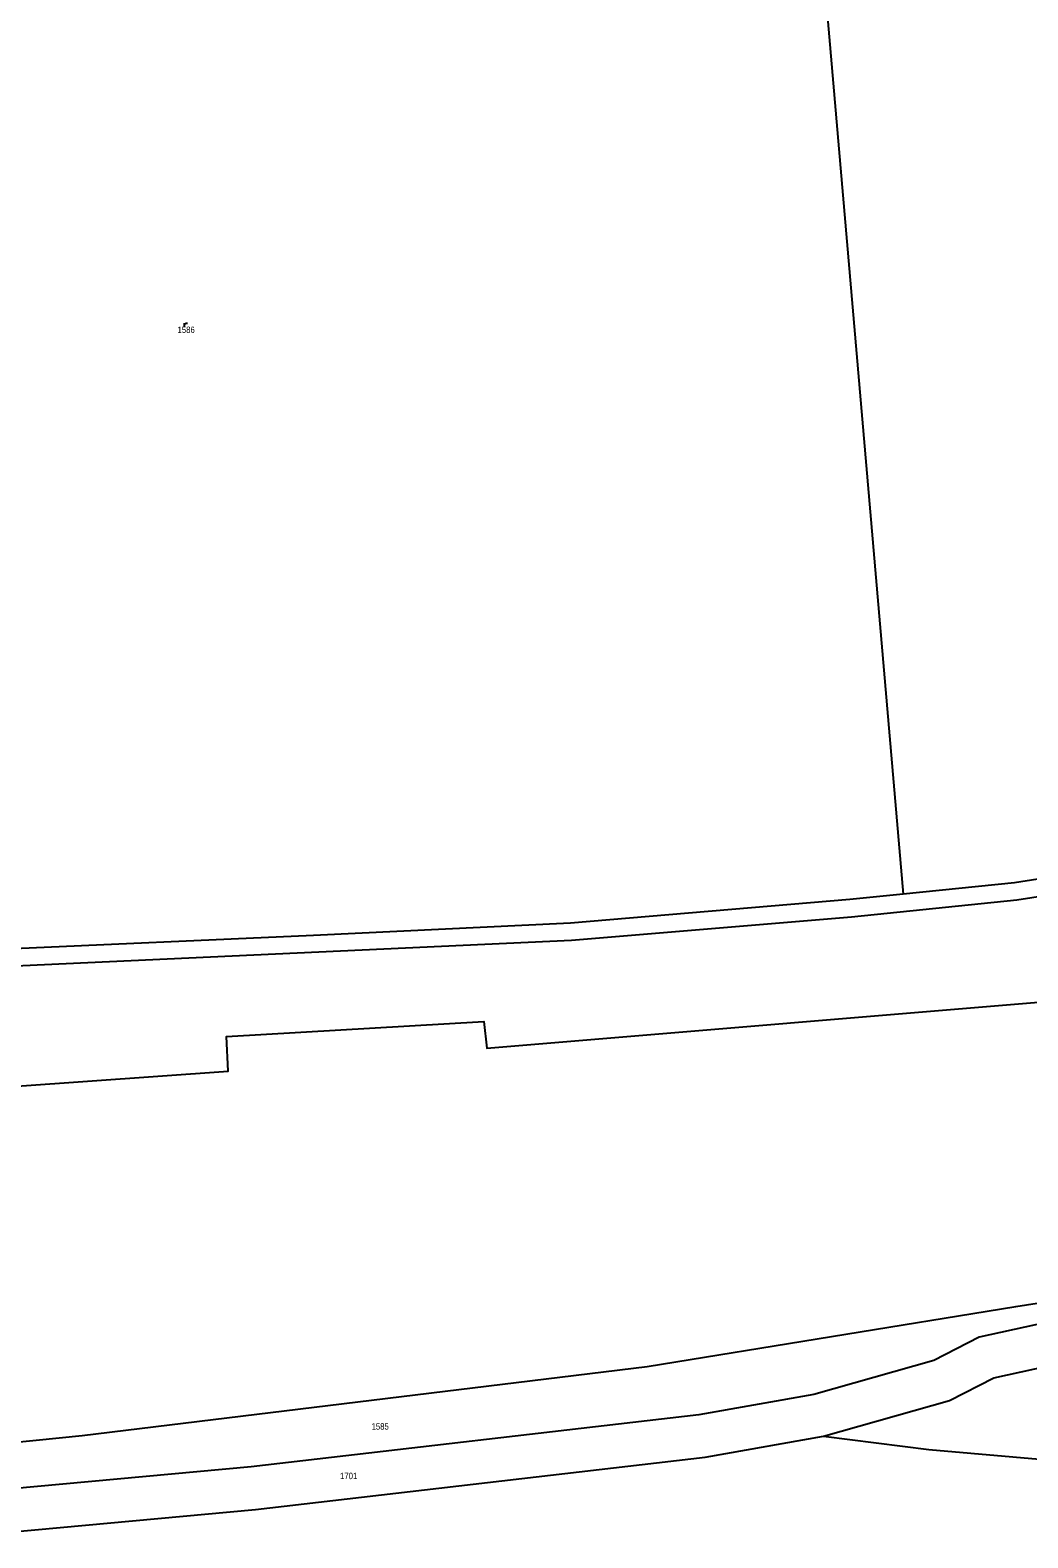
# Model space of a CAD drawing. Extents: x -873052 to -871788, y -1075760 to -1074911.
# Drawn here: x -872666.9 to -872550.4, y -1075585.9 to -1075409.8 of the extents above; entities that cross this region are included whole.
import ezdxf
from ezdxf.enums import TextEntityAlignment as Align

# ---------------------------------------------------------------- set-up
doc = ezdxf.new("R2010")
doc.units = 0
doc.header["$LTSCALE"] = 0.3
doc.layers.add('1', color=7, linetype='Continuous', lineweight=25)
doc.layers.add('25', color=7, linetype='Continuous', lineweight=25)
doc.layers.add('18', color=7, linetype='Continuous')

msp = doc.modelspace()

# ---------------------------------------------------------------- linework, layer by layer
at = {"layer": '1'}
for points in [[(-872670.29, -1075519.13), (-872603.67, -1075516.06), (-872570.99, -1075513.32), (-872551.67, -1075511.35), (-872538.38, -1075509.27), (-872519.75, -1075503.32), (-872512.06, -1075500.18), (-872477.67, -1075483.87), (-872434.28, -1075461.99), (-872418.27, -1075453.02), (-872406.07, -1075444.11), (-872388.59, -1075428.17), (-872372.28, -1075414.6), (-872357.84, -1075404.1), (-872302.51, -1075368.91), (-872288.48, -1075362.95), (-872276.38, -1075357.94), (-872254.7, -1075350.33), (-872243.27, -1075347.56)], [(-872808.66, -1075437.63), (-872810.64, -1075396.3), (-872771.55, -1075392.17), (-872725.26, -1075387.33), (-872576.3, -1075378.91), (-872564.93, -1075510.69)], [(-872373.51, -1075413.02), (-872389.9, -1075426.66), (-872407.34, -1075442.56), (-872419.35, -1075451.33), (-872435.22, -1075460.22), (-872478.55, -1075482.07), (-872512.87, -1075498.35), (-872520.43, -1075501.44), (-872538.84, -1075507.32), (-872551.93, -1075509.37), (-872564.93, -1075510.69)], [(-872564.93, -1075510.69), (-872571.18, -1075511.33), (-872603.8, -1075514.06), (-872633.81, -1075515.5), (-872670.56, -1075517.14)], [(-872698.89, -1075532.77), (-872668.42, -1075533.1), (-872643.77, -1075531.38), (-872643.97, -1075527.32), (-872613.91, -1075525.57), (-872613.56, -1075528.66), (-872543.08, -1075522.8)], [(-872574.25, -1075574.02), (-872559.52, -1075569.83), (-872554.36, -1075567.17), (-872508.79, -1075557.19), (-872455.06, -1075549.61)], [(-872774.15, -1075586.39), (-872753.85, -1075586.1), (-872736.78, -1075586.6), (-872726.39, -1075590.46), (-872640.59, -1075582.55), (-872588.07, -1075576.45), (-872574.25, -1075574.02)], [(-872574.25, -1075574.02), (-872561.94, -1075575.56), (-872542.34, -1075577.26), (-872513.65, -1075576.29), (-872510.45, -1075604.61), (-872463.05, -1075597.7), (-872409.66, -1075624.31), (-872376.95, -1075648.47)]]:
    msp.add_lwpolyline(points, dxfattribs=at)
msp.add_lwpolyline([(-872509.66, -1075552.26), (-872556.08, -1075562.43), (-872561.37, -1075565.16), (-872575.37, -1075569.14), (-872588.79, -1075571.5), (-872641.1, -1075577.58), (-872725.73, -1075585.37), (-872735.81, -1075581.63), (-872744.07, -1075580.4), (-872708.06, -1075578.71), (-872660.84, -1075573.94), (-872594.85, -1075565.87), (-872551.8, -1075558.86)], close=True, dxfattribs=at)
at = {"layer": '25'}
msp.add_line((-872648.88, -1075444.38), (-872648.88, -1075443.989), dxfattribs=at)
msp.add_lwpolyline([(-872648.88, -1075444.112), (-872648.826, -1075444.059), (-872648.767, -1075444.025), (-872648.683, -1075444.003), (-872648.604, -1075443.989), (-872648.519, -1075443.983)], dxfattribs=at)

# ---------------------------------------------------------------- texts
at = {"layer": '18', "width": 0.9}
for s, p in [('1586', (-872648.6795, -1075445.135)), ('1585', (-872626.0195, -1075573.235)), ('1701', (-872629.6995, -1075579.025))]:
    msp.add_text(s, height=0.75, dxfattribs=at).set_placement(p, align=Align.CENTER)

doc.saveas('drawing.dxf')
